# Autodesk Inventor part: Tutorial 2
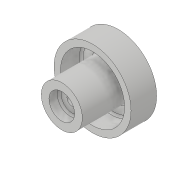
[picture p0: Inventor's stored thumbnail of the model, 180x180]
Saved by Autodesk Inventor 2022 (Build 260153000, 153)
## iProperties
Created: 2017-04
Part Number: Tutorial 2
Material: Generic
Document SubType Name: Modeling
Designer: CADCIM 00
Density: 1 g/cm^3
Appearance: Default
Author: CADCIM 00
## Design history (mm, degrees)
sketch "Sketch1"
  geometry: L1 (0, 0)-(-22, 0); L2 (-22, 0)-(-22, 4); L3 (-22, 4)-(-36, 4); L4 (-36, 4)-(-36, 8.5); L5 (-37.5, 10)-(-44, 10); L6 (-44, 10)-(-44, 16); L7 (-44, 16)-(-5.5, 16); L8 (-4, 17.5)-(-4, 23.5); L9 (-5.5, 25)-(-20, 25); L10 (-20, 25)-(-20, 30); L11 (-20, 30)-(0, 30); L12 (0, 30)-(0, 0); A1 r 1.5 centre (-5.5, 23.5) between (-4, 23.5) and (-5.5, 25); A2 r 1.5 centre (-37.5, 8.5) between (-36, 8.5) and (-37.5, 10); A3 r 1.5 centre (-5.5, 17.5) between (-5.5, 16) and (-4, 17.5)
  constraints: 24 end point, 11 perpendicular, 6 point on circle, 6 tangent, 3 centre point, 2 equal radius, 1 horizontal
  dimensions: "d0" = 8 diameter of L3 L1; "d1" = 20 diameter of L5 L1; "d2" = 32 diameter of L7 L1; "d3" = 50 diameter of L9 L1; "d4" = 60 diameter of L11 L1; "d5" = 4 distance between parallel lines of L8 L12; "d6" = 20 distance of L10.end L11.end; "d7" = 22 distance of L1.start L1.end; "d9" = 36 distance between parallel lines of L4 L12; "d10" = 44 distance between parallel lines of L12 L6; "d11" = 1.5 radius of A1
revolve "Revolution1" sketch "Sketch1" stored, may be unused: angle "d12" = 90 deg
body "Solid1"
